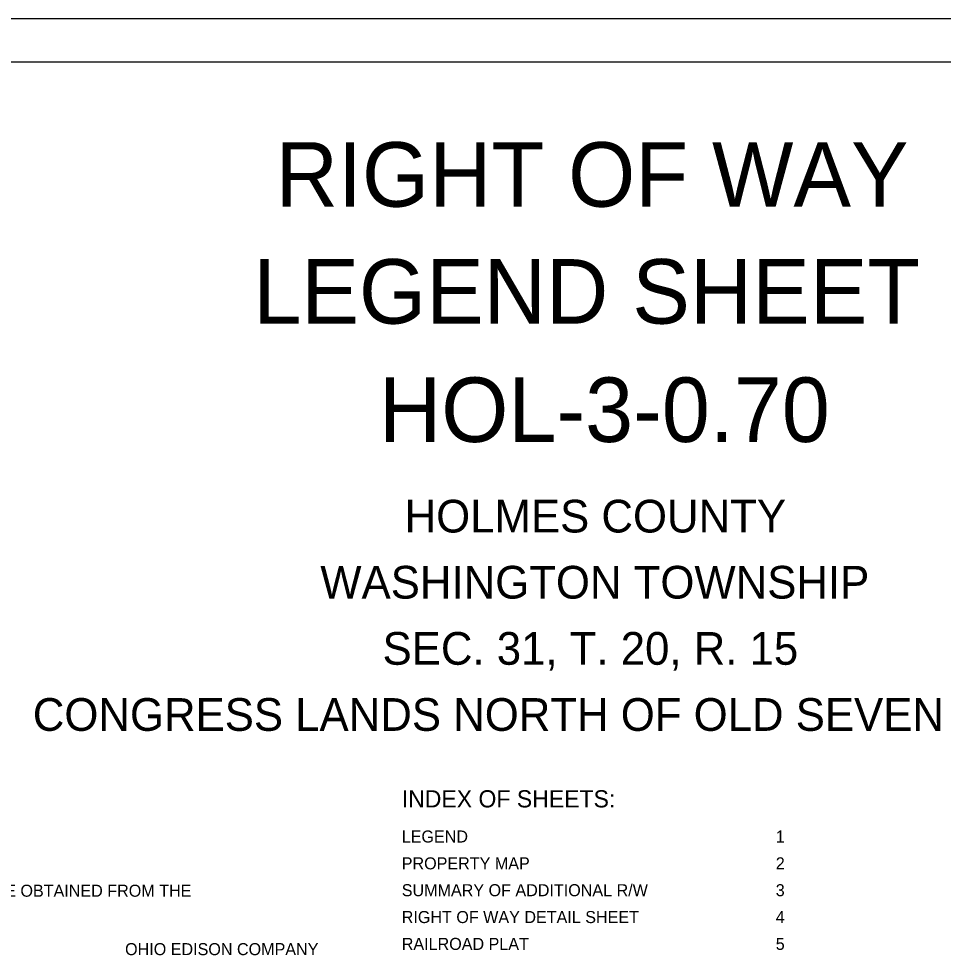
# Model space of a CAD drawing. Extents: x 0 to 34, y 0 to 22.
# Drawn here: x 9.24 to 19.98, y 11.08 to 22 of the extents above; entities that cross this region are included whole.
import ezdxf

# ---------------------------------------------------------------- set-up
doc = ezdxf.new("R2010")
doc.units = 0
for name, color, linetype in [('SH_Border', 7, 'Continuous'), ('SH_Cut_Line', 7, 'Continuous'), ('SH_Data', 7, 'Continuous'), ('SH_Text', 7, 'Continuous')]:
    doc.layers.add(name, color=color, linetype=linetype)

msp = doc.modelspace()

# ---------------------------------------------------------------- linework, layer by layer
at = {"layer": 'SH_Border'}
msp.add_lwpolyline([(1.5, 21.5), (33.5, 21.5), (33.5, 0.5), (1.5, 0.5)], close=True, dxfattribs=at)
at = {"layer": 'SH_Cut_Line'}
msp.add_lwpolyline([(0, 0), (34, 0), (34, 22), (0, 22)], close=True, dxfattribs=at)

# ---------------------------------------------------------------- texts
at = {"layer": 'SH_Data'}
for s, height, p in [('RIGHT OF WAY', 0.75, (12.227, 19.816)), ('LEGEND SHEET', 0.75, (11.968, 18.457)), ('    HOL-3-0.70   ', 0.75, (12.312, 17.082)), ('     HOLMES COUNTY     ', 0.38, (13.019, 16.03)), ('  WASHINGTON TOWNSHIP  ', 0.38, (12.463, 15.262)), ('            SEC. 31, T. 20, R. 15            ', 0.38, (11.775, 14.493)), ('   CONGRESS LANDS NORTH OF OLD SEVEN RANGES  ', 0.38, (8.981, 13.725)), ('INDEX OF SHEETS:', 0.2, (13.692, 12.835)), ('LEGEND                             ', 0.14, (13.692, 12.427)), ('1     ', 0.14, (18.038, 12.427)), ('PROPERTY MAP                       ', 0.14, (13.692, 12.115)), ('2     ', 0.14, (18.038, 12.115)), ('SUMMARY OF ADDITIONAL R/W          ', 0.14, (13.692, 11.803)), ('3     ', 0.14, (18.038, 11.803)), ('RIGHT OF WAY DETAIL SHEET          ', 0.14, (13.692, 11.491)), ('4     ', 0.14, (18.038, 11.491)), ('RAILROAD PLAT                      ', 0.14, (13.692, 11.179)), ('5     ', 0.14, (18.038, 11.179))]:
    msp.add_text(s, height=height, dxfattribs=at).set_placement(p)
at = {"layer": 'SH_Text'}
for s, p in [('THE LOCATION OF THE UNDERGROUND UTILITIES SHOWN ON THE PLANS ARE OBTAINED FROM THE', (1.98, 11.797)), ('OHIO EDISON COMPANY', (10.477, 11.118))]:
    msp.add_text(s, height=0.14, dxfattribs=at).set_placement(p)

doc.saveas('drawing.dxf')
